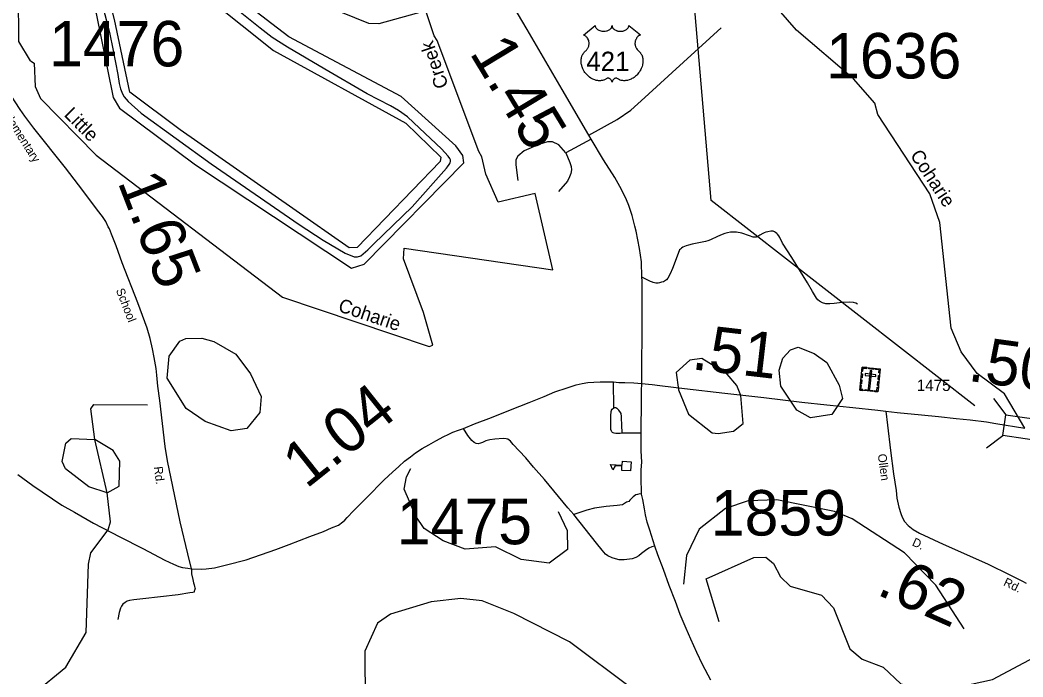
# Model space of a CAD drawing. Extents: x 2093524 to 2270757, y 289120 to 570408.
# Drawn here: x 2149355 to 2160382, y 516355 to 523580 of the extents above; entities that cross this region are included whole.
import ezdxf

# ---------------------------------------------------------------- set-up
doc = ezdxf.new("R2010")
doc.units = 0
for name, color, linetype in [('Exist Cultural Cemetery CELL', 7, 'Continuous'), ('Exist Cultural Educational Facility High CELL', 7, 'Continuous'), ('Exist Hydrographic Creek Single Shore', 7, 'Continuous'), ('Exist Hydrographic Creek Single Shore Label', 7, 'Continuous'), ('Exist Hydrographic Misc Water Feature', 7, 'Continuous'), ('Exist Hydrographic Pond Under 1500 Sq Ft', 7, 'Continuous'), ('Exist Road Non-System Type 51', 7, 'Continuous'), ('Exist Road Primary US Attributed', 7, 'Continuous'), ('Exist Road Primary US Mileage Hundredths English Label', 7, 'Continuous'), ('Exist Road Primary US Shield CELL', 7, 'Continuous'), ('Exist Road Primary US Shield Number Label', 7, 'Continuous'), ('Exist Road Secondary Mileage Hundredths English Label', 7, 'Continuous'), ('Exist Road Secondary Structure Standard Bridge CELL', 7, 'Continuous'), ('Exist Road Secondary Structure Standard Bridge Number Label', 7, 'Continuous'), ('Exist Road Secondary Type 41 Attributed', 7, 'Continuous'), ('Exist Road Secondary Type 51 Attributed', 7, 'Continuous'), ('Exist Road Secondary Type 51 Label', 7, 'Continuous'), ('Exist Road Secondary Type 51 Number Label', 7, 'Continuous')]:
    doc.layers.add(name, color=color, linetype=linetype)

msp = doc.modelspace()

# ---------------------------------------------------------------- linework, layer by layer
at = {"layer": 'Exist Cultural Cemetery CELL'}
for points in [[(2158615, 519763), (2158813, 519742), (2158786, 519489), (2158588, 519510)], [(2158602, 519646), (2158607, 519689), (2158618, 519688), (2158614, 519645)], [(2158610, 519720), (2158621, 519719), (2158625, 519751), (2158665, 519746), (2158666, 519758), (2158615, 519763)], [(2158648, 519691), (2158646, 519672), (2158763, 519660), (2158765, 519679)], [(2158720, 519722), (2158702, 519724), (2158680, 519523), (2158699, 519521)], [(2158688, 519755), (2158740, 519750), (2158739, 519738), (2158687, 519744)], [(2158808, 519699), (2158797, 519700), (2158800, 519732), (2158760, 519736), (2158761, 519748), (2158813, 519742)], [(2158595, 519579), (2158600, 519622), (2158611, 519621), (2158607, 519578)], [(2158782, 519562), (2158787, 519605), (2158798, 519604), (2158794, 519561)], [(2158789, 519628), (2158794, 519671), (2158805, 519669), (2158801, 519626)], [(2158621, 519506), (2158622, 519518), (2158600, 519520), (2158605, 519560), (2158593, 519561), (2158588, 519510)], [(2158646, 519515), (2158731, 519506), (2158730, 519495), (2158645, 519504)], [(2158753, 519492), (2158754, 519504), (2158776, 519501), (2158780, 519542), (2158792, 519541), (2158786, 519489)]]:
    msp.add_lwpolyline(points, close=True, dxfattribs=at)
at = {"layer": 'Exist Cultural Educational Facility High CELL'}
msp.add_lwpolyline([(2156068, 518621), (2155970, 518627), (2155973, 518673), (2155898, 518678), (2155871, 518632), (2155846, 518691), (2155974, 518683), (2155977, 518728), (2156074, 518722)], close=True, dxfattribs=at)
at = {"layer": 'Exist Hydrographic Creek Single Shore'}
for points in [[(2160404, 519090), (2160178, 519468), (2159877, 519691), (2159701, 519931), (2159591, 520189), (2159468, 521353), (2159358, 521670), (2158786, 522541), (2158752, 522666), (2158517, 522933), (2157890, 523470), (2157496, 523925), (2157369, 524117), (2157326, 524492), (2157200, 524708)], [(2149470, 523131), (2149511, 523104), (2149521, 522848), (2149580, 522716), (2150192, 522093), (2152242, 520530), (2153852, 519989), (2153894, 520005), (2153792, 520364), (2153572, 520953), (2153580, 521071), (2155214, 520831), (2155017, 521672), (2154610, 521578), (2154475, 521883), (2154432, 522077), (2154398, 522133), (2153942, 523356), (2153908, 523406), (2153815, 523680), (2153299, 523537), (2153191, 523542), (2152573, 523791)]]:
    msp.add_lwpolyline(points, dxfattribs=at)
at = {"layer": 'Exist Hydrographic Misc Water Feature'}
for points in [[(2149457, 525313), (2149573, 525396), (2149657, 525398), (2149707, 525305), (2149725, 525147), (2149784, 525031), (2149937, 524441), (2150013, 524265), (2150124, 523810), (2150191, 523652), (2150380, 522726), (2150447, 522610), (2151284, 521989), (2152998, 520850), (2153139, 520893), (2154233, 522009), (2154224, 522091), (2154148, 522198), (2153545, 522738), (2152309, 523396), (2150250, 524976), (2150008, 525125), (2149890, 525432)], [(2149470, 523131), (2149340, 523344), (2149337, 523869), (2149262, 523946), (2149203, 524062), (2149211, 524245), (2149035, 524426), (2149059, 524550), (2149457, 525313)], [(2152972, 521076), (2151115, 522373), (2150563, 522788), (2150392, 523585), (2150247, 524169), (2150222, 524186), (2150068, 524825), (2150118, 524824), (2150746, 524362), (2152143, 523245), (2153597, 522445), (2153982, 522073), (2153974, 522024), (2153063, 521078), (2152972, 521076)], [(2150176, 518968), (2150132, 519303), (2150166, 519352), (2150757, 519346)], [(2155270, 518173), (2155372, 517964), (2155373, 517758), (2155174, 517607), (2154865, 517646), (2154581, 517787), (2154248, 517761), (2154006, 517851), (2153797, 517989), (2153705, 518122), (2153578, 518420), (2153602, 518554), (2153652, 518648)], [(2149509, 516176), (2149857, 516461), (2150080, 516844), (2150109, 517595), (2150133, 517719), (2150323, 517971), (2150348, 518062), (2150313, 518378)], [(2159734, 516883), (2159424, 517365), (2159080, 517719), (2158503, 518092), (2158311, 518174), (2157677, 518302), (2157361, 518292), (2157111, 518208), (2156821, 517981), (2156681, 517689), (2156650, 517374)], [(2157043, 516960), (2156899, 517432), (2157422, 517667), (2157556, 517671), (2157639, 517604), (2157715, 517455), (2157824, 517354), (2158166, 517255), (2158300, 517115), (2158478, 516665), (2158612, 516551), (2158846, 516461), (2159038, 516280), (2159180, 516244), (2159663, 516241), (2160046, 516325), (2160735, 516695), (2161100, 517000), (2161508, 517041), (2161690, 517142), (2161864, 517319), (2162181, 517371), (2162347, 517457)], [(2156081, 516228), (2155395, 516740), (2154785, 517054), (2154435, 517193), (2154201, 517217), (2153876, 517181), (2153427, 517046), (2153286, 516947), (2153147, 516638), (2153150, 516070)]]:
    msp.add_lwpolyline(points, dxfattribs=at)
at = {"layer": 'Exist Hydrographic Pond Under 1500 Sq Ft'}
msp.add_line((2150313, 518378), (2150176, 518968), dxfattribs=at)
for points in [[(2151675, 519062), (2151391, 519166), (2151182, 519308), (2150972, 519640), (2150996, 519883), (2151111, 520048), (2151178, 520076), (2151353, 520082), (2151486, 520043), (2151729, 519904), (2151888, 519688), (2152006, 519439), (2151990, 519262), (2151850, 519088), (2151675, 519062)], [(2158047, 519206), (2157897, 519288), (2157720, 519554), (2157702, 519728), (2157743, 519862), (2157826, 519952), (2157909, 519980), (2158085, 519914), (2158227, 519813), (2158361, 519564), (2158396, 519416), (2158280, 519241), (2158047, 519206)], [(2157032, 519033), (2157198, 519059), (2157306, 519142), (2157279, 519451), (2157237, 519560), (2157128, 519684), (2156852, 519857), (2156719, 519840), (2156570, 519705), (2156596, 519514), (2156705, 519246), (2156965, 519041), (2157032, 519033)], [(2150313, 518378), (2150112, 518444), (2149853, 518643), (2149819, 518725), (2149860, 518925), (2149918, 518976), (2150176, 518968)], [(2150313, 518378), (2150445, 518454), (2150452, 518729), (2150377, 518845), (2150176, 518968)]]:
    msp.add_lwpolyline(points, dxfattribs=at)
at = {"layer": 'Exist Road Non-System Type 51'}
for p, q in [((2155633, 522268), (2155355, 522118)), ((2155884, 519313), (2155878, 519599)), ((2156184, 519035), (2155975, 519035))]:
    msp.add_line(p, q, dxfattribs=at)
for points in [[(2150234, 523843), (2150340, 523444), (2150380, 523243), (2150429, 522979), (2150446, 522883), (2150461, 522823), (2150475, 522788), (2150485, 522760), (2150500, 522734), (2150544, 522685), (2150688, 522556), (2151457, 521997), (2152424, 521332), (2152686, 521159), (2152928, 521017), (2153028, 520974), (2153066, 520974), (2153102, 520985), (2153180, 521053), (2153243, 521118), (2153665, 521524), (2154043, 521950), (2154056, 521967), (2154074, 521992), (2154083, 522008), (2154087, 522023), (2154088, 522042), (2154082, 522058), (2154061, 522084), (2153987, 522163), (2153748, 522391), (2153615, 522516), (2153516, 522583), (2153428, 522636), (2153172, 522769), (2152705, 523038), (2152297, 523280), (2152127, 523388), (2151996, 523491), (2151776, 523667)], [(2155608, 522315), (2155921, 522486), (2156070, 522587), (2156225, 522729), (2156526, 523003), (2157063, 523495)], [(2155355, 522118), (2155280, 522206), (2155208, 522239), (2155153, 522239), (2155057, 522212), (2154896, 522143), (2154827, 522083), (2154806, 522043), (2154806, 521988), (2154827, 521815)], [(2155355, 522118), (2155400, 522014), (2155413, 521969), (2155418, 521932), (2155410, 521891), (2155397, 521854), (2155374, 521808), (2155274, 521695)], [(2158562, 520455), (2158546, 520466), (2158517, 520473), (2158475, 520477), (2158393, 520472), (2158305, 520463), (2158257, 520459), (2158215, 520460), (2158179, 520468), (2158143, 520489), (2158126, 520503), (2158111, 520521), (2158068, 520593), (2158011, 520690), (2157842, 520969), (2157738, 521127), (2157708, 521187), (2157697, 521205), (2157683, 521223), (2157674, 521233), (2157661, 521244), (2157649, 521252), (2157637, 521256), (2157624, 521257), (2157611, 521256), (2157576, 521250), (2157556, 521245), (2157538, 521238), (2157523, 521231), (2157490, 521213), (2157466, 521199), (2157456, 521194), (2157447, 521190), (2157436, 521190), (2157425, 521190), (2157414, 521193), (2157374, 521206), (2157292, 521236), (2157233, 521246), (2157203, 521248), (2157167, 521246), (2157135, 521241), (2157104, 521232), (2157073, 521221), (2157023, 521200), (2156948, 521164), (2156917, 521152), (2156892, 521145), (2156746, 521113), (2156705, 521105), (2156678, 521097), (2156660, 521089), (2156643, 521080), (2156627, 521071), (2156615, 521061), (2156607, 521052), (2156601, 521040), (2156527, 520847), (2156503, 520787), (2156478, 520741), (2156464, 520723), (2156452, 520714), (2156440, 520706), (2156429, 520702), (2156406, 520695), (2156386, 520690), (2156372, 520687), (2156358, 520686), (2156345, 520686), (2156329, 520688), (2156317, 520692), (2156308, 520695), (2156288, 520704), (2156193, 520750)], [(2155975, 519035), (2155954, 519033), (2155925, 519033), (2155905, 519033), (2155887, 519037), (2155875, 519041), (2155869, 519044), (2155863, 519050), (2155857, 519058), (2155852, 519076), (2155852, 519211), (2155852, 519239), (2155853, 519262), (2155854, 519277), (2155856, 519282), (2155858, 519289), (2155866, 519299), (2155884, 519313)], [(2155975, 519035), (2155970, 519127), (2155967, 519201), (2155966, 519229), (2155965, 519238), (2155965, 519245), (2155963, 519253), (2155957, 519265), (2155940, 519288), (2155922, 519305), (2155916, 519309), (2155906, 519313), (2155896, 519315), (2155884, 519313)], [(2155443, 518143), (2155378, 518216), (2155275, 518341), (2155121, 518528), (2155000, 518663), (2154915, 518764), (2154841, 518840), (2154778, 518911), (2154746, 518947), (2154719, 518969), (2154700, 518972), (2154665, 518976), (2154574, 518971), (2154520, 518963), (2154476, 518951), (2154440, 518934), (2154418, 518926), (2154390, 518918), (2154370, 518922), (2154346, 518934), (2154322, 518957), (2154277, 519009), (2154230, 519086)], [(2156189, 518365), (2156170, 518367), (2156142, 518360), (2156125, 518356), (2156097, 518334), (2156059, 518300), (2156049, 518284), (2156023, 518276), (2155977, 518249), (2155920, 518239), (2155800, 518230), (2155672, 518211), (2155588, 518188), (2155508, 518163), (2155443, 518143)], [(2156335, 517794), (2156303, 517784), (2156270, 517771), (2156232, 517747), (2156188, 517713), (2156158, 517686), (2156125, 517670), (2156085, 517654), (2155997, 517643), (2155941, 517643), (2155901, 517652), (2155865, 517664), (2155816, 517685), (2155790, 517705), (2155756, 517749), (2155693, 517827), (2155443, 518143)], [(2151240, 517545), (2151240, 517488), (2151255, 517426), (2151263, 517391), (2151269, 517369), (2151274, 517349), (2151278, 517334), (2151280, 517327), (2151276, 517317), (2151274, 517305), (2151270, 517299), (2151268, 517289), (2151256, 517284), (2151222, 517280), (2151092, 517259), (2150705, 517214), (2150605, 517203), (2150559, 517194), (2150531, 517190), (2150511, 517174), (2150485, 517154), (2150470, 517134), (2150460, 517112), (2150446, 517065), (2150429, 516987)]]:
    msp.add_lwpolyline(points, dxfattribs=at)
at = {"layer": 'Exist Road Primary US Attributed'}
for points in [[(2156192, 519581), (2156196, 520338), (2156194, 520712), (2156193, 520750), (2156186, 520922), (2156165, 521068), (2156129, 521257), (2156116, 521313), (2156086, 521429), (2156047, 521539), (2156021, 521604), (2155968, 521715), (2155894, 521847), (2155768, 522044), (2155633, 522268), (2155608, 522315), (2155317, 522817), (2154930, 523477), (2154301, 524548)], [(2156950, 516319), (2156859, 516492), (2156796, 516622), (2156730, 516769), (2156679, 516889), (2156614, 517040), (2156561, 517186), (2156493, 517359), (2156428, 517535), (2156368, 517696), (2156335, 517794), (2156278, 517970), (2156251, 518057), (2156230, 518139), (2156222, 518205), (2156203, 518305), (2156189, 518365), (2156186, 518439), (2156185, 518483), (2156185, 518541), (2156184, 518633), (2156190, 518717), (2156184, 518841), (2156185, 518961), (2156184, 519035), (2156184, 519137), (2156186, 519305), (2156189, 519501), (2156192, 519581)]]:
    msp.add_lwpolyline(points, dxfattribs=at)
at = {"layer": 'Exist Road Primary US Shield CELL'}
msp.add_lwpolyline([(2155680, 523518), (2155680, 523513), (2155681, 523506), (2155682, 523503), (2155685, 523497), (2155690, 523489), (2155697, 523482), (2155705, 523476), (2155710, 523473), (2155719, 523468), (2155729, 523464), (2155740, 523460), (2155751, 523458), (2155763, 523457), (2155776, 523457), (2155789, 523458), (2155803, 523460), (2155810, 523462), (2155818, 523465), (2155825, 523468), (2155832, 523472), (2155838, 523476), (2155843, 523479), (2155850, 523486), (2155856, 523492), (2155858, 523496), (2155860, 523500), (2155863, 523508), (2155863, 523511), (2155864, 523518), (2155864, 523512), (2155865, 523508), (2155866, 523505), (2155867, 523501), (2155870, 523495), (2155873, 523491), (2155879, 523484), (2155882, 523481), (2155886, 523478), (2155894, 523472), (2155905, 523467), (2155910, 523465), (2155915, 523463), (2155921, 523461), (2155928, 523459), (2155935, 523458), (2155942, 523457), (2155949, 523457), (2155954, 523457), (2155961, 523457), (2155968, 523457), (2155974, 523458), (2155982, 523459), (2155988, 523460), (2155995, 523462), (2156002, 523465), (2156008, 523467), (2156016, 523472), (2156023, 523476), (2156028, 523479), (2156033, 523485), (2156038, 523491), (2156042, 523495), (2156044, 523500), (2156046, 523505), (2156047, 523510), (2156048, 523514), (2156048, 523518), (2156176, 523416), (2156173, 523415), (2156166, 523411), (2156161, 523408), (2156152, 523402), (2156148, 523398), (2156144, 523395), (2156141, 523391), (2156138, 523387), (2156134, 523382), (2156131, 523377), (2156128, 523371), (2156125, 523366), (2156121, 523356), (2156119, 523350), (2156118, 523344), (2156117, 523333), (2156116, 523327), (2156116, 523322), (2156116, 523316), (2156117, 523310), (2156118, 523305), (2156119, 523300), (2156121, 523294), (2156123, 523286), (2156126, 523280), (2156131, 523268), (2156139, 523257), (2156144, 523251), (2156150, 523245), (2156158, 523238), (2156162, 523235), (2156167, 523230), (2156175, 523220), (2156178, 523216), (2156182, 523211), (2156185, 523206), (2156188, 523200), (2156190, 523196), (2156195, 523185), (2156198, 523174), (2156199, 523168), (2156202, 523156), (2156203, 523149), (2156204, 523137), (2156204, 523122), (2156203, 523108), (2156200, 523092), (2156198, 523082), (2156194, 523070), (2156191, 523060), (2156185, 523046), (2156180, 523035), (2156173, 523023), (2156169, 523015), (2156163, 523007), (2156156, 522998), (2156149, 522988), (2156139, 522977), (2156131, 522970), (2156121, 522961), (2156115, 522956), (2156107, 522949), (2156095, 522941), (2156083, 522935), (2156073, 522929), (2156064, 522926), (2156053, 522921), (2156034, 522916), (2156027, 522915), (2156019, 522913), (2156011, 522913), (2156004, 522912), (2155994, 522912), (2155984, 522913), (2155974, 522914), (2155965, 522916), (2155954, 522919), (2155945, 522923), (2155936, 522928), (2155920, 522938), (2155915, 522940), (2155912, 522941), (2155906, 522941), (2155901, 522940), (2155895, 522938), (2155891, 522936), (2155886, 522933), (2155883, 522930), (2155878, 522926), (2155875, 522922), (2155873, 522919), (2155868, 522912), (2155867, 522909), (2155865, 522905), (2155864, 522898), (2155862, 522906), (2155859, 522912), (2155857, 522916), (2155854, 522920), (2155849, 522925), (2155845, 522929), (2155840, 522933), (2155835, 522936), (2155831, 522938), (2155827, 522940), (2155823, 522941), (2155819, 522941), (2155816, 522941), (2155811, 522940), (2155806, 522936), (2155800, 522932), (2155794, 522929), (2155787, 522925), (2155782, 522922), (2155775, 522920), (2155768, 522917), (2155760, 522915), (2155752, 522914), (2155745, 522913), (2155737, 522912), (2155730, 522912), (2155723, 522912), (2155716, 522912), (2155709, 522913), (2155699, 522914), (2155691, 522916), (2155682, 522919), (2155674, 522921), (2155664, 522925), (2155653, 522930), (2155644, 522934), (2155632, 522942), (2155617, 522952), (2155605, 522961), (2155597, 522969), (2155585, 522981), (2155578, 522989), (2155566, 523004), (2155559, 523014), (2155554, 523022), (2155548, 523035), (2155544, 523042), (2155539, 523054), (2155535, 523064), (2155532, 523074), (2155530, 523080), (2155528, 523091), (2155526, 523099), (2155525, 523110), (2155524, 523121), (2155524, 523132), (2155524, 523140), (2155525, 523150), (2155527, 523161), (2155529, 523170), (2155531, 523177), (2155533, 523185), (2155537, 523194), (2155541, 523202), (2155545, 523210), (2155550, 523217), (2155556, 523224), (2155562, 523231), (2155569, 523237), (2155575, 523242), (2155583, 523250), (2155586, 523254), (2155591, 523260), (2155595, 523266), (2155598, 523271), (2155602, 523279), (2155604, 523284), (2155607, 523293), (2155609, 523299), (2155610, 523307), (2155611, 523314), (2155611, 523323), (2155611, 523331), (2155610, 523340), (2155609, 523348), (2155607, 523356), (2155603, 523364), (2155600, 523370), (2155595, 523379), (2155590, 523387), (2155584, 523393), (2155579, 523399), (2155573, 523403), (2155568, 523407), (2155561, 523411), (2155555, 523414), (2155551, 523415)], close=True, dxfattribs=at)
at = {"layer": 'Exist Road Secondary Structure Standard Bridge CELL'}
for p, q in [((2160058, 519419), (2160194, 519238)), ((2159980, 518873), (2160161, 519009))]:
    msp.add_line(p, q, dxfattribs=at)
msp.add_lwpolyline([(2160194, 519238), (2160685, 519168), (2160652, 518938), (2160161, 519009)], close=True, dxfattribs=at)
at = {"layer": 'Exist Road Secondary Structure Standard Bridge Number Label'}
msp.add_lwpolyline([(2159854, 519335), (2156955, 521594), (2156766, 523778)], dxfattribs=at)
at = {"layer": 'Exist Road Secondary Type 41 Attributed'}
msp.add_lwpolyline([(2158874, 519278), (2158891, 519124), (2158926, 518844), (2158959, 518590), (2158987, 518407), (2158996, 518321), (2159018, 518221), (2159038, 518153), (2159052, 518111), (2159081, 518065), (2159119, 518021), (2159175, 517977), (2159243, 517935), (2159505, 517814), (2159992, 517597), (2160243, 517473), (2160377, 517408), (2160417, 517388)], dxfattribs=at)
at = {"layer": 'Exist Road Secondary Type 51 Attributed'}
for points in [[(2151240, 517545), (2151201, 517709), (2151117, 518061), (2151033, 518451), (2150976, 518730), (2150951, 518891), (2150891, 519394), (2150870, 519552), (2150859, 519673), (2150850, 519747), (2150829, 519870), (2150811, 519964), (2150784, 520078), (2150753, 520191), (2150651, 520469), (2150477, 520911), (2150411, 521095), (2150362, 521223), (2150337, 521282), (2150322, 521307), (2150297, 521363), (2150260, 521420), (2150208, 521489), (2150045, 521705), (2149855, 521955), (2149505, 522391), (2149408, 522522), (2149355, 522596), (2149252, 522755)], [(2151240, 517545), (2151348, 517539), (2151400, 517542), (2151492, 517553), (2151624, 517586), (2151841, 517644), (2152166, 517758), (2152314, 517812), (2152541, 517898), (2152692, 517955), (2152778, 517994), (2152856, 518024), (2152905, 518059), (2152925, 518079), (2152953, 518107), (2153022, 518180), (2153163, 518323), (2153359, 518521), (2153449, 518606), (2153518, 518670), (2153582, 518727), (2153647, 518777), (2153703, 518818), (2153776, 518867), (2153848, 518907), (2153928, 518952), (2154015, 519001), (2154063, 519023), (2154114, 519047), (2154177, 519068), (2154230, 519086), (2154352, 519139), (2154539, 519209), (2154746, 519293), (2154952, 519375), (2155117, 519438), (2155235, 519489), (2155369, 519534), (2155470, 519569), (2155536, 519584), (2155598, 519592), (2155662, 519597), (2155732, 519599), (2155780, 519600), (2155828, 519600), (2155878, 519599), (2155938, 519595), (2156004, 519594), (2156104, 519591), (2156192, 519581)], [(2156192, 519581), (2156265, 519576), (2156306, 519570), (2156389, 519559), (2156660, 519526), (2157104, 519477), (2157532, 519427), (2157950, 519377), (2158226, 519349), (2158512, 519317), (2158786, 519288), (2158874, 519278)], [(2158874, 519278), (2158998, 519265), (2159265, 519237), (2159453, 519218), (2159647, 519197), (2159801, 519184), (2159981, 519160), (2160082, 519142), (2160404, 519090)], [(2149330, 518582), (2149495, 518462), (2149816, 518245), (2149953, 518166), (2150164, 518045), (2150451, 517894), (2150706, 517766), (2150945, 517640), (2151042, 517595), (2151100, 517571), (2151142, 517560), (2151198, 517550), (2151240, 517545)]]:
    msp.add_lwpolyline(points, dxfattribs=at)

# ---------------------------------------------------------------- texts
at = {"layer": 'Exist Hydrographic Creek Single Shore Label'}
for s, rotation, p in [('Creek', 108.9014, (2154067, 522856)), ('Little', 314.5098, (2149830, 522532)), ('Coharie', 303.2992, (2159136, 522093)), ('Coharie', 341.4343, (2152843, 520380))]:
    msp.add_text(s, height=150, rotation=rotation, dxfattribs=at).set_placement(p)
at = {"layer": 'Exist Road Primary US Mileage Hundredths English Label'}
msp.add_text('1.45', height=500, rotation=301.1482, dxfattribs=at).set_placement((2154290, 523220))
at = {"layer": 'Exist Road Primary US Shield Number Label'}
msp.add_text('421', height=212.5, dxfattribs=at).set_placement((2155581, 523019))
at = {"layer": 'Exist Road Secondary Mileage Hundredths English Label'}
for s, rotation, p in [('1.65', 291.1602, (2150424, 521801)), ('.51', 353.3848, (2156729, 519740)), ('.50', 352.2105, (2159766, 519613)), ('1.04', 38.5337, (2152502, 518417)), ('.62', 336.0713, (2158759, 517268))]:
    msp.add_text(s, height=500, rotation=rotation, dxfattribs=at).set_placement(p)
at = {"layer": 'Exist Road Secondary Type 51 Label'}
for s, rotation, p in [('Elementary', 302.5343, (2149160, 522545)), ('School', 291.1602, (2150407, 520609)), ('Ollen', 277.3934, (2158785, 518803)), ('Rd.', 276.7426, (2150827, 518665)), ('D.', 335.1703, (2159155, 517804)), ('Rd.', 334.2057, (2160159, 517365))]:
    msp.add_text(s, height=95, rotation=rotation, dxfattribs=at).set_placement(p)
at = {"layer": 'Exist Road Secondary Type 51 Number Label'}
for s, height, p in [('1476', 500, (2149673, 523070)), ('1636', 500, (2158217, 522937)), ('1475', 125, (2159214, 519500)), ('1859', 500, (2156949, 517910)), ('1475', 500, (2153497, 517814))]:
    msp.add_text(s, height=height, dxfattribs=at).set_placement(p)

doc.saveas('drawing.dxf')
